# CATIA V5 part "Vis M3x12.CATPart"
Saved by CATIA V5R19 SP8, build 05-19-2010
Part number: Vis M3x12
Nomenclature:  MAKER100359
Publications: "Mating Face", "Axis"
Bounding box of the stored display mesh (mm): x -12 to 1.764, y -3.2 to 3.2, z -3.2 to 3.2
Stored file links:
  D:\Documents\1_Travail\1 - ac-limoges.fr\ac-limoges.fr\Emmanuel Maynard - STI2D_Turgot\1 - IT-I2D\Activités_IT_Première\IT_3_Abris_bus\Maquettes numériques\Abribus_eleve\Vis M3x12.CATPart
  C:\Program Files\Dassault Systemes\B19\win_b64\startup\components\MechanicalStandardParts\EN_Standards\Design_Tables\EN_ISO_4762_HEXAGON_SOCKET_HEAD_CAP_SCREW.txt
  C:\Program Files\Dassault Systemes\B19\win_b64\startup\components\MechanicalStandardParts\ISO_Standards\Design_Tables\ISO_4762_HEXAGON_SOCKET_HEAD_CAP_SCREW.txt
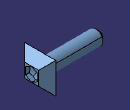
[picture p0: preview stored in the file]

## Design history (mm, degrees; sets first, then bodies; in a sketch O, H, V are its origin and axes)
Parameters
  d_dia = 3 mm
  l_nom = 6 mm
  k_head_depth_max = 3 mm
  s_nom = 2.5 mm
  r_min = 0.1 mm
  ds_max = 3 mm
  e = 2.873 mm
  t_min = 1.3 mm
  p_pitch = 0.5 mm
  Threading = 4.5 mm
  dk_max = 5.5 mm
Set1
  Plane1: type Offset, RefPlane start face of Pad1, Offset 0.5
  Plane2: type OffsetPt, RefPlane Plane1, RefPoint vertex [face of Pad2 from Sketch3.L3 | face of Pad1 from Sketch1.L4 | face of Shaft2 from Sketch4.L2]
Body1 "PartBody" (main body)
  Sketch1 on yz-plane, origin (0, 0, 0), H (0, 1, 0), V (0, 0, 1)
    line L1 (2.7, 2.7) -> (2.7, -2.7)
    line L2 (2.7, -2.7) -> (-2.7, -2.7)
    line L3 (-2.7, -2.7) -> (-2.7, 2.7)
    line L4 (-2.7, 2.7) -> (2.7, 2.7)
    distance L4 L2 = 5.4
    distance L1 L3 = 5.4
    vertical: L1 V, L3 V
    horizontal: L2 H, L4 H
    equidistance: L1 L3 O, L2 L4 O
  Pad1: profile Sketch1, direction (1, 0, 0), length 3 {= k_head_depth_max}
  Sketch2 on xy-plane, origin (0, 0, 0), H (1, 0, 0), V (0, 1, 0)
    line L1 (0, 0) -> (0, 1.5)
    line L2 (0, 1.5) -> (-1, 1.5)
    line L3 (-1, 1.5) -> (-1, 1.4634)
    line L4 (-1, 1.4634) -> (-12, 1.4634)
    line L5 (-12, 1.4634) -> (-12, 0)
    axis line L6 (-192.3446, 0) -> (99.1594, 0)
    distance L5 L1 = 12
    distance L3 L5 = 11
    distance L2 L6 = 1.5 {= ds_max /2}
    distance L4 L6 = 1.4634 {= d_dia /2.05}
    vertical: L1 V, L3 V, L5 V
    horizontal: L2 H, L4 H, L6 H
    fix: L6
  Shaft1: profile Sketch2, axis Sketch2.L6, angle 360
  Fillet1: radius 0.1 {= r_min}, on edge [face of Shaft1 | face of Pad1]
  Chamfer1: length 0.5 {= p_pitch}, angle 45, on edge [face of Shaft1 | face of Shaft1]
  Thread1: diameter 2.9268 {= d_dia /1.025}, depth 4.5 {= Threading}, pitch 1, on face of Shaft1, from face of Shaft1
  Draft1: PullDir start face of Pad1, Angle -45, SupportToDraft (face of Pad1 from Sketch1.L1; face of Pad1 from Sketch1.L2; face of Pad1 from Sketch1.L3; face of Pad1 from Sketch1.L4), Neutral Plane1
  Body2
    Sketch3 on face of Pad1, origin (3, 0, 0), H (0, 1, 0), V (0, 0, 1)
      point P1 (1.25, -0.7217)
      point P2 (1.25, 0.7217)
      point P3 (0, 1.4434)
      point P4 (-1.25, 0.7217)
      point P5 (-1.25, -0.7217)
      point P6 (0, -1.4434)
      point P7 (1.25, 0)
      line L1 (1.25, -0.7217) -> (1.25, 0.7217)
      line L2 (1.25, 0.7217) -> (0, 1.4434)
      line L3 (0, 1.4434) -> (-1.25, 0.7217)
      line L4 (-1.25, 0.7217) -> (-1.25, -0.7217)
      line L5 (-1.25, -0.7217) -> (0, -1.4434)
      line L6 (0, -1.4434) -> (1.25, -0.7217)
      construction line L7 (0, 0) -> (1.25, 0)
      construction circle A1 centre (0, 0) radius 1.4434
      construction arc A2 centre (-1.25, -0.7217) radius 1.4434 from (-1.25, 0.7217) to (0, -1.4434) cw
      construction arc A3 centre (1.25, 0.7217) radius 1.4434 from (0, 1.4434) to (1.25, -0.7217) ccw
      point P8 (-1.25, -0.7217)
      point P9 (1.25, 0.7217)
      distance L1 L4 = 2.5 {= s_nom}
      horizontal: L7 H
      coincidence: A1 P1, A1 P2, A1 P3, A1 P4, A1 P5, A1 P6, A2 P4, A2 P6, A2 O, P8 P5, A3 P3, A3 P1, A3 O, P9 P2
      midpoint: P7 L1
    Pad2: profile Sketch3, direction (-1, 0, 0), length 3
    Body3
      Sketch4 on zx-plane, origin (0, 0, 0), H (-1, 0, 0), V (0, 0, 1)
        point P1 (-0.1706, 0)
        line L1 (-0.1706, 0) -> (-1, 1.4365)
        line L2 (-1, 1.4365) -> (-3, 1.4365)
        line L3 (-3, 1.4365) -> (-3, 0)
        axis line L4 (-46.2384, 0) -> (26.3409, 0)
        reference projected line E1 (-3, -6.9227) -> (-3, 6.9227) from edge [face of Pad2 | face of Pad2]
        length L2 = 2
        angle L1 L4 = 60
        distance L2 L4 = 1.4365 {= e /2}
        horizontal: L2 H, L4 H
        perpendicularity: L3 L2
        fix: L4
        coincidence: L3 E1, P1 L4
      Shaft2: profile Sketch4, axis Sketch4.L4, angle 360
    Intersect1: tool Body3
  Remove1: tool Body2
  Split1: SplitPlane Plane2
